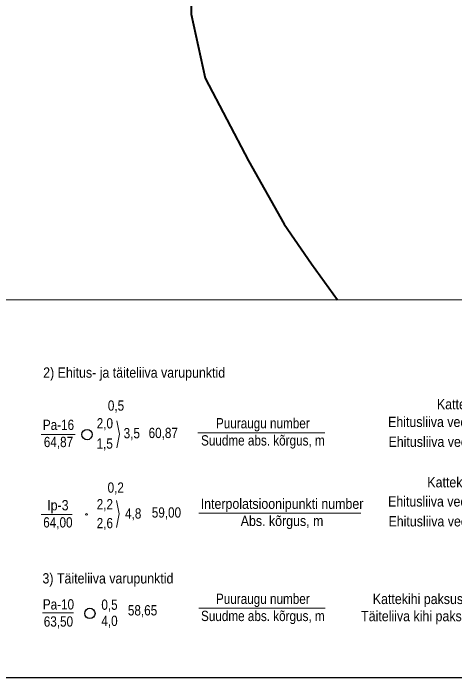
# Model space of a CAD drawing. Extents: x 628176 to 629009, y 6439913 to 6440496.
# Drawn here: x 628597.9 to 628726.4, y 6439918.5 to 6440112.2 of the extents above; entities that cross this region are included whole.
import ezdxf
from ezdxf.enums import TextEntityAlignment as Align

# ---------------------------------------------------------------- set-up
doc = ezdxf.new("R2010")
doc.units = 0
doc.header["$LTSCALE"] = 0.8
doc.layers.add('20', color=7, linetype='Continuous', lineweight=40)
doc.layers.add('50', color=7, linetype='Continuous', lineweight=13)

msp = doc.modelspace()

# ---------------------------------------------------------------- linework, layer by layer
at = {"layer": '20'}
msp.add_lwpolyline([(628650.11, 6440140.45), (628649.71, 6440111.91), (628653.77, 6440093.25), (628666.38, 6440069.11), (628676.78, 6440050.71), (628684.75, 6440039.11), (628692.3, 6440028.67)], dxfattribs=at)
at = {"layer": '50'}
for p, q in [((628606.01, 6439989.41), (628615.94, 6439989.41)), ((628651.64, 6439989.83), (628688.56, 6439989.83)), ((628606.01, 6439966.01), (628615, 6439966.01)), ((628651.86, 6439966.44), (628699.08, 6439966.44)), ((628651.87, 6439938.74), (628688.72, 6439938.74)), ((628606.42, 6439937.34), (628615.41, 6439937.34))]:
    msp.add_line(p, q, dxfattribs=at)
at = {"layer": '50', "lineweight": 25}
msp.add_lwpolyline([(628178.27, 6440495.9), (629008.51, 6440495.9), (629008.51, 6439918.47), (628178.27, 6439918.47)], close=True, dxfattribs=at)
at = {"layer": '50'}
msp.add_lwpolyline([(628214.18, 6440472.45), (628760.23, 6440472.45), (628760.23, 6440028.67), (628214.18, 6440028.67)], close=True, dxfattribs=at)
for points in [[(628628, 6439993.35), (628628.81, 6439989.43), (628628, 6439985.45)], [(628627.92, 6439970.12), (628628.73, 6439966.2), (628627.92, 6439962.22)]]:
    msp.add_lwpolyline(points, dxfattribs=at)
at = {"layer": '50', "lineweight": 25}
for centre in [(628619.348, 6439989.3371), (628620.1932, 6439937.2231)]:
    msp.add_circle(centre, 1.5, dxfattribs=at)
at = {"layer": '50'}
msp.add_circle((628619.2064, 6439966.0857), 0.25, dxfattribs=at)

# ---------------------------------------------------------------- texts
for s, width, p in [('2) Ehitus- ja täiteliiva varupunktid', 0.9, (628633.075, 6440005.92)), ('0,5', 0.85, (628627.79, 6439996.31)), ('Kattekihi paksus, m', 0.9, (628736.885, 6439996.7)), ('Puuraugu number', 0.85, (628670.545, 6439991.16)), ('Ehitusliiva veepealse kihi paksus, m', 0.9, (628735.8, 6439991.55)), ('Pa-16', 0.85, (628611.04, 6439990.69)), ('2,0', 0.85, (628624.545, 6439991.13)), ('3,5', 0.85, (628632.39, 6439988.26)), ('60,87', 0.85, (628641.55, 6439988.33)), ('64,87', 0.85, (628611.035, 6439985.69)), ('Suudme abs. kõrgus, m', 0.85, (628670.555, 6439986.16)), ('Ehitusliiva veealuse kihi paksus, m', 0.9, (628734.925, 6439985.76)), ('1,5', 0.85, (628624.5, 6439985.23)), ('Kattekihi paksus, m', 0.9, (628734.09, 6439973.95)), ('0,2', 0.85, (628627.71, 6439972.4)), ('Ehitusliiva veepealse kihi paksus, m', 0.9, (628735.8, 6439968.37)), ('Ip-3', 0.9, (628610.87, 6439967.25)), ('2,2', 0.85, (628624.545, 6439967.55)), ('Interpolatsioonipunkti number', 0.9, (628676.135, 6439967.69)), ('4,8', 0.85, (628632.805, 6439964.86)), ('59,00', 0.85, (628642.47, 6439965.14)), ('64,00', 0.85, (628610.87, 6439962.25)), ('Abs. kõrgus, m', 0.9, (628676.135, 6439962.69)), ('Ehitusliiva veealuse kihi paksus, m', 0.9, (628734.925, 6439962.57)), ('2,6', 0.85, (628624.545, 6439962.04)), ('3) Täiteliiva varupunktid', 0.9, (628625.44, 6439945.94)), ('Puuraugu number', 0.85, (628670.54, 6439939.98)), ('Kattekihi paksus, m', 0.9, (628718.215, 6439939.94)), ('Pa-10', 0.85, (628611.03, 6439938.36)), ('0,5', 0.85, (628625.895, 6439938.26)), ('58,65', 0.85, (628635.52, 6439936.62)), ('Suudme abs. kõrgus, m', 0.85, (628670.545, 6439934.98)), ('Täiteliiva kihi paksus, m', 0.9, (628718.225, 6439934.94)), ('63,50', 0.85, (628611.025, 6439933.36)), ('4,0', 0.85, (628625.9, 6439933.55))]:
    msp.add_text(s, height=3, dxfattribs=dict(at, width=width)).set_placement(p, align=Align.CENTER)

doc.saveas('drawing.dxf')
